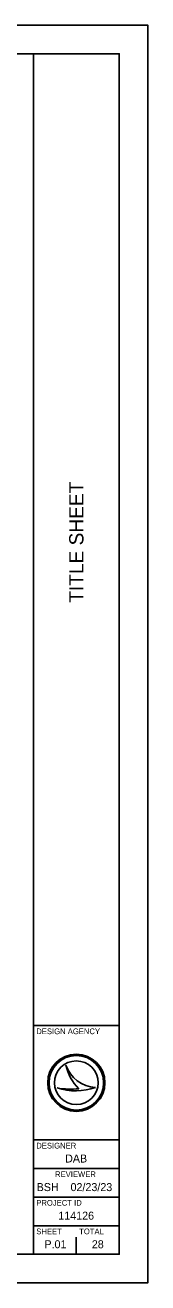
# Model space of a CAD drawing. Extents: x -7.5 to 53.5, y 0 to 22.
# Drawn here: x 31.86 to 34, y 0 to 22 of the extents above; entities that cross this region are included whole.
import ezdxf

# ---------------------------------------------------------------- set-up
doc = ezdxf.new("R2010")
doc.units = 0
for name, color, linetype in [('SH_Border', 7, 'Continuous'), ('SH_Cut_Line', 7, 'Continuous'), ('SH_Data', 7, 'Continuous')]:
    doc.layers.add(name, color=color, linetype=linetype)

msp = doc.modelspace()

# ---------------------------------------------------------------- linework, layer by layer
at = {"layer": 'SH_Border'}
for p, q in [((32, 0.5), (32, 21.5)), ((32, 4.5), (33.5, 4.5)), ((32, 2.5), (33.5, 2.5)), ((32, 2), (33.5, 2)), ((32, 1.5), (33.5, 1.5)), ((32, 1), (33.5, 1))]:
    msp.add_line(p, q, dxfattribs=at)
msp.add_lwpolyline([(1.5, 21.5), (33.5, 21.5), (33.5, 0.5), (1.5, 0.5)], close=True, dxfattribs=at)
at = {"layer": 'SH_Cut_Line'}
msp.add_lwpolyline([(0, 0), (34, 0), (34, 22), (0, 22)], close=True, dxfattribs=at)
at = {"layer": 'SH_Data'}
for p, q in [((32.567, 3.81), (32.567, 3.81)), ((32.567, 3.81), (32.567, 3.81)), ((32.417, 3.41), (32.417, 3.41)), ((32.417, 3.41), (32.417, 3.41)), ((32.75, 3.5), (32.75, 3.5)), ((33.087, 3.419), (33.087, 3.419)), ((33.087, 3.419), (33.087, 3.419)), ((32.375, 0.675), (32.375, 0.675)), ((32.75, 0.5), (32.75, 0.8))]:
    msp.add_line(p, q, dxfattribs=at)
for radius in [0.5, 0.5, 0.477, 0.477, 0.477, 0.477, 0.382, 0.382]:
    msp.add_circle((32.75, 3.5), radius, dxfattribs=at)
for centre, radius, start, end in [((33.116, 3.998), 0.58, 198.9257, 198.9319), ((33.347, 3.97), 0.796, 191.6379, 191.6421), ((33.116, 3.998), 0.58, 198.9319, 267.1657), ((33.347, 3.97), 0.796, 191.6421, 226.0947), ((33.116, 3.998), 0.58, 198.9257, 198.9319), ((33.347, 3.97), 0.796, 191.6379, 191.6421), ((33.116, 3.998), 0.58, 198.9319, 267.1657), ((33.347, 3.97), 0.796, 191.6421, 226.0947), ((32.739, 4.37), 1.013, 251.4576, 290.0832), ((32.739, 4.37), 1.013, 251.4576, 290.0832), ((32.648, 4.654), 1.266, 259.4964, 259.4995), ((32.739, 4.37), 1.013, 251.4527, 251.4576), ((32.648, 4.654), 1.266, 259.4964, 259.4995), ((32.739, 4.37), 1.013, 251.4527, 251.4576), ((32.648, 4.654), 1.266, 259.4995, 276.6672), ((32.648, 4.654), 1.266, 259.4995, 276.6672)]:
    msp.add_arc(centre, radius, start, end, dxfattribs=at)

# ---------------------------------------------------------------- texts
msp.add_text('TITLE SHEET', height=0.25, rotation=90, dxfattribs=at).set_placement((32.875, 11.897))
for s, height, p in [('DESIGN AGENCY', 0.1, (32.05, 4.35)), ('DESIGNER', 0.1, (32.05, 2.35)), ('DAB', 0.14, (32.554, 2.105)), ('REVIEWER', 0.1, (32.378, 1.85)), ('BSH', 0.14, (32.057, 1.605)), ('02/23/23', 0.14, (32.649, 1.605)), ('PROJECT ID', 0.1, (32.05, 1.35)), ('114126', 0.14, (32.435, 1.105)), ('SHEET', 0.1, (32.05, 0.85)), ('TOTAL', 0.1, (32.8, 0.85)), ('P.01', 0.14, (32.192, 0.605)), ('28', 0.14, (33.021, 0.605))]:
    msp.add_text(s, height=height, dxfattribs=at).set_placement(p)

doc.saveas('drawing.dxf')
